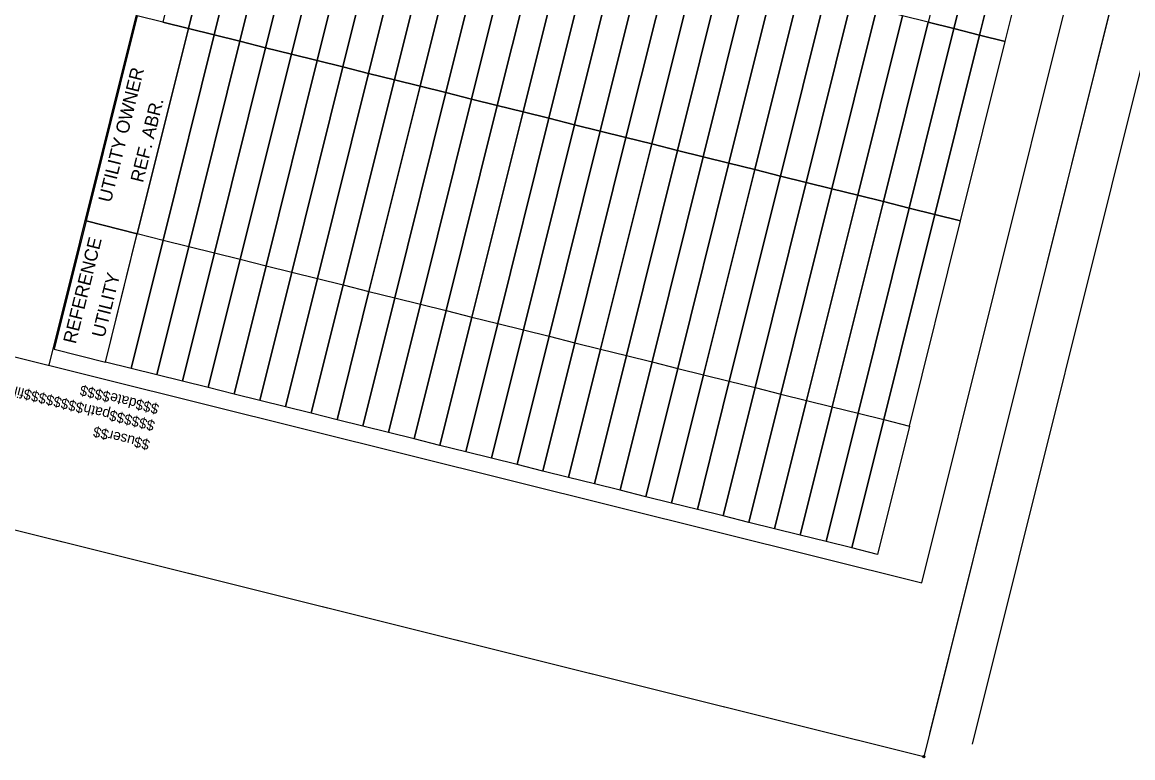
# Model space of a CAD drawing. Extents: x 2304552 to 2306093, y 413849 to 415858.
# Drawn here: x 2305126 to 2305759, y 413849 to 414268 of the extents above; entities that cross this region are included whole.
import ezdxf

# ---------------------------------------------------------------- set-up
doc = ezdxf.new("R2010")
doc.units = 0
for name, color, linetype in [('RD_SHT_Bndy', 7, 'Continuous'), ('RD_SHT_ID', 7, 'Continuous'), ('RD_SHT_Iplotshp', 7, 'Continuous'), ('RD_SHT_MjGrid', 7, 'Continuous'), ('RD_SHT_Snap', 7, 'Continuous'), ('RD_SHT_TX', 7, 'Continuous')]:
    doc.layers.add(name, color=color, linetype=linetype)

msp = doc.modelspace()

# ---------------------------------------------------------------- linework, layer by layer
at = {"layer": 'RD_SHT_Bndy'}
for p, q in [((2305141.49, 414072.62), (2305546.41, 415697.93)), ((2305638.78, 413948.72), (2306043.71, 415574.04)), ((2306068.61, 415570.57), (2305643.14, 413862.77)), ((2306092.87, 415564.52), (2305667.39, 413856.73)), ((2304619.93, 414202.56), (2305638.78, 413948.72))]:
    msp.add_line(p, q, dxfattribs=at)
at = {"layer": 'RD_SHT_Iplotshp'}
msp.add_lwpolyline([(2304572.49, 414115.54), (2305006.64, 415858.18), (2306074.01, 415592.25), (2305639.86, 413849.62)], close=True, dxfattribs=at)
msp.add_circle((2305639.86, 413849.62), 0.607, dxfattribs=at)
at = {"layer": 'RD_SHT_MjGrid'}
for points in [[(2305220.78, 414264.53), (2305246.26, 414366.77), (2305231.64, 414370.41), (2305206.17, 414268.17)], [(2305246.26, 414366.77), (2305220.78, 414264.53), (2305235.45, 414260.88), (2305260.92, 414363.11)], [(2305260.92, 414363.11), (2305235.45, 414260.88), (2305250.12, 414257.22), (2305275.59, 414359.46)], [(2305275.59, 414359.46), (2305250.12, 414257.22), (2305264.79, 414253.57), (2305290.26, 414355.8)], [(2305290.26, 414355.8), (2305264.79, 414253.57), (2305279.45, 414249.91), (2305304.92, 414352.15)], [(2305304.92, 414352.15), (2305279.45, 414249.91), (2305294.12, 414246.26), (2305319.59, 414348.5)], [(2305319.59, 414348.5), (2305294.12, 414246.26), (2305308.79, 414242.6), (2305334.26, 414344.84)], [(2305334.26, 414344.84), (2305308.79, 414242.6), (2305323.45, 414238.95), (2305348.92, 414341.19)], [(2305348.92, 414341.19), (2305323.45, 414238.95), (2305338.12, 414235.3), (2305363.59, 414337.53)], [(2305363.59, 414337.53), (2305338.12, 414235.3), (2305352.79, 414231.64), (2305378.26, 414333.88)], [(2305660.46, 414341.14), (2305642.27, 414268.11), (2305656.93, 414264.45), (2305675.13, 414337.48)], [(2305675.13, 414337.48), (2305656.93, 414264.45), (2305671.6, 414260.8), (2305689.79, 414333.83)], [(2305378.26, 414333.88), (2305352.79, 414231.64), (2305367.45, 414227.99), (2305392.93, 414330.23)], [(2305689.79, 414333.83), (2305671.6, 414260.8), (2305686.27, 414257.14), (2305704.46, 414330.17)], [(2305392.93, 414330.23), (2305367.45, 414227.99), (2305382.12, 414224.33), (2305407.59, 414326.57)], [(2305407.59, 414326.57), (2305382.12, 414224.33), (2305396.79, 414220.68), (2305422.26, 414322.92)], [(2305422.26, 414322.92), (2305396.79, 414220.68), (2305411.46, 414217.03), (2305436.93, 414319.26)], [(2305436.93, 414319.26), (2305411.46, 414217.03), (2305426.12, 414213.37), (2305451.59, 414315.61)], [(2305451.59, 414315.61), (2305426.12, 414213.37), (2305440.79, 414209.72), (2305466.26, 414311.96)], [(2305466.26, 414311.96), (2305440.79, 414209.72), (2305455.46, 414206.06), (2305480.93, 414308.3)], [(2305480.93, 414308.3), (2305455.46, 414206.06), (2305470.12, 414202.41), (2305495.6, 414304.65)], [(2305495.6, 414304.65), (2305470.12, 414202.41), (2305484.79, 414198.76), (2305510.26, 414300.99)], [(2305510.26, 414300.99), (2305484.79, 414198.76), (2305499.46, 414195.1), (2305524.93, 414297.34)], [(2305524.93, 414297.34), (2305499.46, 414195.1), (2305514.13, 414191.45), (2305539.6, 414293.68)], [(2305539.6, 414293.68), (2305514.13, 414191.45), (2305528.79, 414187.79), (2305554.26, 414290.03)], [(2305554.26, 414290.03), (2305528.79, 414187.79), (2305543.46, 414184.14), (2305568.93, 414286.38)], [(2305568.93, 414286.38), (2305543.46, 414184.14), (2305558.13, 414180.48), (2305583.6, 414282.72)], [(2305583.6, 414282.72), (2305558.13, 414180.48), (2305572.79, 414176.83), (2305598.26, 414279.07)], [(2305598.26, 414279.07), (2305572.79, 414176.83), (2305587.46, 414173.18), (2305612.93, 414275.41)], [(2305612.93, 414275.41), (2305587.46, 414173.18), (2305602.13, 414169.52), (2305627.6, 414271.76)], [(2305191.66, 414147.62), (2305220.78, 414264.53), (2305191.55, 414271.81), (2305162.42, 414154.9)], [(2305627.6, 414271.76), (2305602.13, 414169.52), (2305616.79, 414165.87), (2305642.27, 414268.11)], [(2305642.27, 414268.11), (2305616.79, 414165.87), (2305631.46, 414162.21), (2305656.93, 414264.45)], [(2305220.78, 414264.53), (2305191.66, 414147.64), (2305206.33, 414143.98), (2305235.45, 414260.88)], [(2305656.93, 414264.45), (2305631.46, 414162.21), (2305646.13, 414158.56), (2305671.6, 414260.8)], [(2305235.45, 414260.88), (2305206.33, 414143.98), (2305221, 414140.33), (2305250.12, 414257.22)], [(2305250.12, 414257.22), (2305221, 414140.33), (2305235.66, 414136.67), (2305264.79, 414253.57)], [(2305671.6, 414260.8), (2305646.13, 414158.56), (2305660.8, 414154.91), (2305686.27, 414257.14)], [(2305264.79, 414253.57), (2305235.66, 414136.67), (2305250.33, 414133.02), (2305279.45, 414249.91)], [(2305279.45, 414249.91), (2305250.33, 414133.02), (2305265, 414129.37), (2305294.12, 414246.26)], [(2305294.12, 414246.26), (2305265, 414129.37), (2305279.66, 414125.71), (2305308.79, 414242.6)], [(2305308.79, 414242.6), (2305279.66, 414125.71), (2305294.33, 414122.06), (2305323.45, 414238.95)], [(2305323.45, 414238.95), (2305294.33, 414122.06), (2305309, 414118.4), (2305338.12, 414235.3)], [(2305338.12, 414235.3), (2305309, 414118.4), (2305323.67, 414114.75), (2305352.79, 414231.64)], [(2305352.79, 414231.64), (2305323.67, 414114.75), (2305338.33, 414111.09), (2305367.45, 414227.99)], [(2305367.45, 414227.99), (2305338.33, 414111.09), (2305353, 414107.44), (2305382.12, 414224.33)], [(2305382.12, 414224.33), (2305353, 414107.44), (2305367.67, 414103.79), (2305396.79, 414220.68)], [(2305396.79, 414220.68), (2305367.67, 414103.79), (2305382.33, 414100.13), (2305411.46, 414217.03)], [(2305411.46, 414217.03), (2305382.33, 414100.13), (2305397, 414096.48), (2305426.12, 414213.37)], [(2305426.12, 414213.37), (2305397, 414096.48), (2305411.67, 414092.82), (2305440.79, 414209.72)], [(2305440.79, 414209.72), (2305411.67, 414092.82), (2305426.33, 414089.17), (2305455.46, 414206.06)], [(2305455.46, 414206.06), (2305426.33, 414089.17), (2305441, 414085.52), (2305470.12, 414202.41)], [(2305470.12, 414202.41), (2305441, 414085.52), (2305455.67, 414081.86), (2305484.79, 414198.76)], [(2305484.79, 414198.76), (2305455.67, 414081.86), (2305470.34, 414078.21), (2305499.46, 414195.1)], [(2305499.46, 414195.1), (2305470.34, 414078.21), (2305485, 414074.55), (2305514.13, 414191.45)], [(2305514.13, 414191.45), (2305485, 414074.55), (2305499.67, 414070.9), (2305528.79, 414187.79)], [(2305528.79, 414187.79), (2305499.67, 414070.9), (2305514.34, 414067.25), (2305543.46, 414184.14)], [(2305543.46, 414184.14), (2305514.34, 414067.25), (2305529, 414063.59), (2305558.13, 414180.48)], [(2305558.13, 414180.48), (2305529, 414063.59), (2305543.67, 414059.94), (2305572.79, 414176.83)], [(2305572.79, 414176.83), (2305543.67, 414059.94), (2305558.34, 414056.28), (2305587.46, 414173.18)], [(2305587.46, 414173.18), (2305558.34, 414056.28), (2305573.01, 414052.63), (2305602.13, 414169.52)], [(2305602.13, 414169.52), (2305573.01, 414052.63), (2305587.67, 414048.97), (2305616.79, 414165.87)], [(2305616.79, 414165.87), (2305587.67, 414048.97), (2305602.34, 414045.32), (2305631.46, 414162.21)], [(2305631.46, 414162.21), (2305602.34, 414045.32), (2305617.01, 414041.67), (2305646.13, 414158.56)], [(2305173.44, 414074.51), (2305191.66, 414147.62), (2305162.42, 414154.9), (2305144.2, 414081.79)], [(2305646.13, 414158.56), (2305617.01, 414041.67), (2305631.67, 414038.01), (2305660.8, 414154.91)], [(2305173.44, 414074.51), (2305191.66, 414147.64), (2305206.33, 414143.98), (2305188.11, 414070.85)], [(2305188.11, 414070.85), (2305206.33, 414143.98), (2305221, 414140.33), (2305202.78, 414067.2)], [(2305202.78, 414067.2), (2305221, 414140.33), (2305235.66, 414136.67), (2305217.44, 414063.54)], [(2305217.44, 414063.54), (2305235.66, 414136.67), (2305250.33, 414133.02), (2305232.11, 414059.89)], [(2305232.11, 414059.89), (2305250.33, 414133.02), (2305265, 414129.37), (2305246.78, 414056.24)], [(2305246.78, 414056.24), (2305265, 414129.37), (2305279.66, 414125.71), (2305261.44, 414052.58)], [(2305261.44, 414052.58), (2305279.66, 414125.71), (2305294.33, 414122.06), (2305276.11, 414048.93)], [(2305276.11, 414048.93), (2305294.33, 414122.06), (2305309, 414118.4), (2305290.78, 414045.27)], [(2305290.78, 414045.27), (2305309, 414118.4), (2305323.67, 414114.75), (2305305.45, 414041.62)], [(2305305.45, 414041.62), (2305323.67, 414114.75), (2305338.33, 414111.09), (2305320.11, 414037.96)], [(2305320.11, 414037.96), (2305338.33, 414111.09), (2305353, 414107.44), (2305334.78, 414034.31)], [(2305334.78, 414034.31), (2305353, 414107.44), (2305367.67, 414103.79), (2305349.45, 414030.66)], [(2305349.45, 414030.66), (2305367.67, 414103.79), (2305382.33, 414100.13), (2305364.11, 414027)], [(2305364.11, 414027), (2305382.33, 414100.13), (2305397, 414096.48), (2305378.78, 414023.35)], [(2305378.78, 414023.35), (2305397, 414096.48), (2305411.67, 414092.82), (2305393.45, 414019.69)], [(2305393.45, 414019.69), (2305411.67, 414092.82), (2305426.33, 414089.17), (2305408.12, 414016.04)], [(2305408.12, 414016.04), (2305426.33, 414089.17), (2305441, 414085.52), (2305422.78, 414012.39)], [(2305422.78, 414012.39), (2305441, 414085.52), (2305455.67, 414081.86), (2305437.45, 414008.73)], [(2305437.45, 414008.73), (2305455.67, 414081.86), (2305470.34, 414078.21), (2305452.12, 414005.08)], [(2305452.12, 414005.08), (2305470.34, 414078.21), (2305485, 414074.55), (2305466.78, 414001.42)], [(2305466.78, 414001.42), (2305485, 414074.55), (2305499.67, 414070.9), (2305481.45, 413997.77)], [(2305481.45, 413997.77), (2305499.67, 414070.9), (2305514.34, 414067.25), (2305496.12, 413994.12)], [(2305496.12, 413994.12), (2305514.34, 414067.25), (2305529, 414063.59), (2305510.78, 413990.46)], [(2305510.78, 413990.46), (2305529, 414063.59), (2305543.67, 414059.94), (2305525.45, 413986.81)], [(2305525.45, 413986.81), (2305543.67, 414059.94), (2305558.34, 414056.28), (2305540.12, 413983.15)], [(2305540.12, 413983.15), (2305558.34, 414056.28), (2305573.01, 414052.63), (2305554.79, 413979.5)], [(2305554.79, 413979.5), (2305573.01, 414052.63), (2305587.67, 414048.97), (2305569.45, 413975.84)], [(2305569.45, 413975.84), (2305587.67, 414048.97), (2305602.34, 414045.32), (2305584.12, 413972.19)], [(2305584.12, 413972.19), (2305602.34, 414045.32), (2305617.01, 414041.67), (2305598.79, 413968.54)], [(2305598.79, 413968.54), (2305617.01, 414041.67), (2305631.67, 414038.01), (2305613.45, 413964.88)]]:
    msp.add_lwpolyline(points, close=True, dxfattribs=at)
at = {"layer": 'RD_SHT_Snap'}
msp.add_line((2305639.86, 413849.62), (2304572.49, 414115.54), dxfattribs=at)

# ---------------------------------------------------------------- texts
at = {"layer": 'RD_SHT_ID'}
for s, p in [('$$$$$$path$$$$$$$$filename$$$$$$$$', (2305202.04, 414040.78)), ('$$$date$$$$', (2305204.41, 414050.29)), ('$$user$$', (2305199.22, 414029.89))]:
    msp.add_text(s, height=5.88, rotation=166.01032, dxfattribs=at).set_placement(p)
at = {"layer": 'RD_SHT_TX'}
for s, p in [('UTILITY OWNER', (2305176.6, 414165.01)), ('REF. ABR.', (2305194.87, 414176.31)), ('REFERENCE', (2305156.53, 414084.47)), ('UTILITY', (2305172.87, 414087.98))]:
    msp.add_text(s, height=7.5, rotation=76.01032, dxfattribs=at).set_placement(p)

doc.saveas('drawing.dxf')
